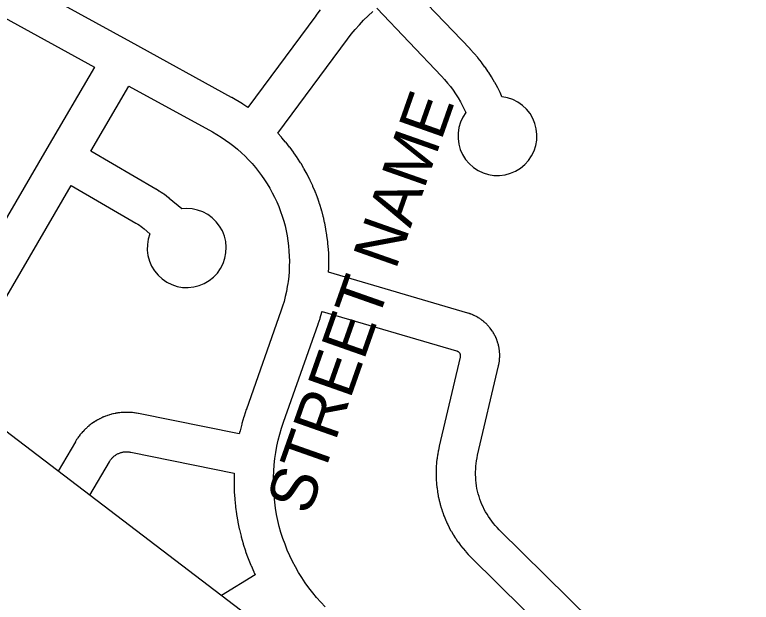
# Model space of a CAD drawing. Extents: x 599744 to 600217, y 4827560 to 4828065.
# Drawn here: x 600005.99 to 600017.17, y 4827965.06 to 4827973.98 of the extents above; entities that cross this region are included whole.
import ezdxf

# ---------------------------------------------------------------- set-up
doc = ezdxf.new("R2010")
doc.units = 0
doc.layers.add('G-ANNO-KEYP', color=7, linetype='Continuous')
doc.layers.add('G-TTLB-OTLN', color=7, linetype='Continuous')

msp = doc.modelspace()

# ---------------------------------------------------------------- linework, layer by layer
at = {"layer": 'G-ANNO-KEYP'}
for points in [[(600010.623, 4827974.058), (600010.559, 4827973.974), (600010.559, 4827973.974), (600010.555, 4827973.97), (600009.526, 4827972.575), (600009.523, 4827972.578), (600009.45, 4827972.626), (600009.449, 4827972.626), (600009.442, 4827972.632), (600009.367, 4827972.678), (600009.366, 4827972.678), (600009.358, 4827972.683), (600009.283, 4827972.726), (600009.282, 4827972.727), (600009.278, 4827972.729), (600007.753, 4827973.568), (600006.144, 4827974.453)], [(600013.694, 4827972.609), (600013.625, 4827972.657), (600013.549, 4827972.696), (600013.469, 4827972.723), (600013.386, 4827972.739), (600013.383, 4827972.74), (600013.359, 4827972.794), (600013.356, 4827972.797), (600013.354, 4827972.803), (600013.319, 4827972.875), (600013.316, 4827972.878), (600013.314, 4827972.884), (600013.276, 4827972.954), (600013.273, 4827972.958), (600013.271, 4827972.963), (600013.231, 4827973.032), (600013.227, 4827973.036), (600013.225, 4827973.041), (600013.182, 4827973.108), (600013.178, 4827973.113), (600013.176, 4827973.117), (600013.131, 4827973.183), (600013.127, 4827973.188), (600013.125, 4827973.191), (600013.078, 4827973.255), (600013.073, 4827973.26), (600013.071, 4827973.264), (600013.022, 4827973.326), (600013.016, 4827973.331), (600013.015, 4827973.334), (600012.963, 4827973.394), (600012.957, 4827973.4), (600012.956, 4827973.402), (600012.902, 4827973.461), (600012.899, 4827973.464), (600012.899, 4827973.465), (600011.989, 4827974.419)], [(600011.036, 4827973.613), (600011.095, 4827973.69), (600011.155, 4827973.763), (600011.218, 4827973.834), (600011.283, 4827973.903), (600011.351, 4827973.97), (600011.421, 4827974.034)], [(600011.481, 4827974.085), (600012.463, 4827973.054), (600012.512, 4827973.001), (600012.557, 4827972.948), (600012.6, 4827972.894), (600012.641, 4827972.839), (600012.68, 4827972.782), (600012.717, 4827972.724), (600012.752, 4827972.664), (600012.785, 4827972.604), (600012.815, 4827972.542), (600012.833, 4827972.502), (600012.788, 4827972.43), (600012.753, 4827972.353), (600012.729, 4827972.272), (600012.716, 4827972.188), (600012.716, 4827972.103), (600012.728, 4827972.019), (600012.751, 4827971.937), (600012.786, 4827971.86), (600012.831, 4827971.788), (600012.886, 4827971.724), (600012.95, 4827971.667), (600013.02, 4827971.621), (600013.097, 4827971.584), (600013.178, 4827971.559), (600013.262, 4827971.546), (600013.347, 4827971.544), (600013.431, 4827971.555), (600013.513, 4827971.577), (600013.591, 4827971.611), (600013.663, 4827971.655), (600013.728, 4827971.709), (600013.785, 4827971.771), (600013.833, 4827971.841), (600013.871, 4827971.918), (600013.897, 4827971.998), (600013.912, 4827972.082), (600013.914, 4827972.166), (600013.905, 4827972.251), (600013.884, 4827972.333), (600013.852, 4827972.411), (600013.809, 4827972.484), (600013.756, 4827972.55), (600013.694, 4827972.609)], [(600005.826, 4827973.944), (600007.195, 4827973.191), (600006.474, 4827971.954), (600004.55, 4827968.652)], [(600010.693, 4827970.822), (600010.692, 4827970.823), (600010.69, 4827970.832), (600010.671, 4827970.917), (600010.67, 4827970.918), (600010.668, 4827970.927), (600010.646, 4827971.012), (600010.645, 4827971.013), (600010.643, 4827971.022), (600010.617, 4827971.105), (600010.616, 4827971.107), (600010.614, 4827971.115), (600010.586, 4827971.198), (600010.584, 4827971.2), (600010.582, 4827971.207), (600010.551, 4827971.289), (600010.549, 4827971.292), (600010.547, 4827971.299), (600010.513, 4827971.379), (600010.511, 4827971.382), (600010.509, 4827971.389), (600010.472, 4827971.468), (600010.47, 4827971.471), (600010.468, 4827971.477), (600010.428, 4827971.555), (600010.425, 4827971.559), (600010.424, 4827971.564), (600010.382, 4827971.641), (600010.378, 4827971.645), (600010.376, 4827971.65), (600010.332, 4827971.725), (600010.328, 4827971.73), (600010.326, 4827971.734), (600010.279, 4827971.808), (600010.275, 4827971.812), (600010.273, 4827971.816), (600010.224, 4827971.888), (600010.219, 4827971.893), (600010.218, 4827971.897), (600010.165, 4827971.967), (600010.161, 4827971.972), (600010.159, 4827971.975), (600010.105, 4827972.043), (600010.099, 4827972.049), (600010.098, 4827972.051), (600010.041, 4827972.118), (600010.035, 4827972.123), (600010.034, 4827972.125), (600009.981, 4827972.184), (600011.036, 4827973.613)], [(600008.209, 4827971.286), (600008.176, 4827971.308), (600008.175, 4827971.308), (600008.168, 4827971.313), (600008.134, 4827971.334), (600008.133, 4827971.334), (600008.13, 4827971.336), (600007.142, 4827971.911), (600007.72, 4827972.902), (600008.988, 4827972.205), (600009.056, 4827972.166), (600009.122, 4827972.125), (600009.186, 4827972.082), (600009.249, 4827972.037), (600009.31, 4827971.99), (600009.369, 4827971.941), (600009.428, 4827971.89), (600009.483, 4827971.837), (600009.537, 4827971.781), (600009.59, 4827971.725), (600009.64, 4827971.666), (600009.688, 4827971.606), (600009.734, 4827971.544), (600009.778, 4827971.48), (600009.82, 4827971.415), (600009.859, 4827971.349), (600009.896, 4827971.281), (600009.931, 4827971.212), (600009.963, 4827971.142), (600009.993, 4827971.071), (600010.021, 4827970.999), (600010.046, 4827970.926), (600010.069, 4827970.852), (600010.089, 4827970.777), (600010.106, 4827970.702), (600010.121, 4827970.626), (600010.133, 4827970.55), (600010.143, 4827970.473), (600010.149, 4827970.397), (600010.154, 4827970.319), (600010.155, 4827970.242), (600010.154, 4827970.165), (600010.151, 4827970.088), (600010.145, 4827970.011), (600010.136, 4827969.934), (600010.131, 4827969.902), (600010.124, 4827969.858), (600010.11, 4827969.782), (600010.093, 4827969.707), (600010.074, 4827969.632), (600010.052, 4827969.558), (600010.027, 4827969.483)], [(600005.03, 4827968.286), (600006.841, 4827971.394), (600007.826, 4827970.82), (600007.853, 4827970.803), (600007.878, 4827970.787), (600007.903, 4827970.77), (600007.926, 4827970.753), (600007.951, 4827970.733), (600008.038, 4827970.66)], [(600008.038, 4827970.66), (600008.013, 4827970.579), (600007.999, 4827970.496), (600007.998, 4827970.411), (600008.008, 4827970.327), (600008.03, 4827970.245), (600008.064, 4827970.167), (600008.108, 4827970.095), (600008.162, 4827970.029), (600008.224, 4827969.972), (600008.294, 4827969.924), (600008.37, 4827969.886), (600008.451, 4827969.86), (600008.534, 4827969.845), (600008.619, 4827969.842), (600008.703, 4827969.851), (600008.785, 4827969.872), (600008.864, 4827969.904), (600008.937, 4827969.947), (600009.003, 4827970), (600009.062, 4827970.062), (600009.11, 4827970.131), (600009.149, 4827970.207), (600009.177, 4827970.287), (600009.193, 4827970.37), (600009.197, 4827970.455), (600009.189, 4827970.539), (600009.169, 4827970.622), (600009.138, 4827970.701), (600009.096, 4827970.774), (600009.045, 4827970.841), (600008.984, 4827970.901), (600008.915, 4827970.951), (600008.84, 4827970.99), (600008.761, 4827971.019), (600008.678, 4827971.036), (600008.593, 4827971.042), (600008.522, 4827971.037), (600008.331, 4827971.195), (600008.328, 4827971.198), (600008.328, 4827971.198), (600008.297, 4827971.223), (600008.294, 4827971.226), (600008.289, 4827971.229), (600008.257, 4827971.253), (600008.257, 4827971.253), (600008.249, 4827971.258), (600008.217, 4827971.281), (600008.216, 4827971.281), (600008.209, 4827971.286)], [(600013.065, 4827969.357), (600013.057, 4827969.363), (600013.046, 4827969.371), (600013.045, 4827969.371), (600013.037, 4827969.376), (600013.025, 4827969.384), (600013.024, 4827969.384), (600013.016, 4827969.389), (600013.004, 4827969.396), (600013.002, 4827969.396), (600012.995, 4827969.401), (600012.983, 4827969.407), (600012.98, 4827969.408), (600012.973, 4827969.412), (600012.961, 4827969.418), (600012.958, 4827969.419), (600012.951, 4827969.423), (600012.939, 4827969.428), (600012.935, 4827969.429), (600012.929, 4827969.432), (600012.916, 4827969.437), (600012.912, 4827969.438), (600012.906, 4827969.441), (600012.893, 4827969.445), (600012.889, 4827969.446), (600012.883, 4827969.449), (600012.87, 4827969.453), (600012.868, 4827969.453), (600012.865, 4827969.454), (600010.75, 4827970.075), (600010.753, 4827970.142), (600010.753, 4827970.15), (600010.753, 4827970.152), (600010.754, 4827970.24), (600010.754, 4827970.249), (600010.754, 4827970.25), (600010.752, 4827970.337), (600010.752, 4827970.347), (600010.752, 4827970.348), (600010.747, 4827970.435), (600010.746, 4827970.445), (600010.746, 4827970.445), (600010.738, 4827970.532), (600010.737, 4827970.542), (600010.737, 4827970.543), (600010.726, 4827970.629), (600010.726, 4827970.629), (600010.725, 4827970.64), (600010.711, 4827970.726), (600010.711, 4827970.726), (600010.709, 4827970.736), (600010.693, 4827970.822)], [(600010.027, 4827969.483), (600009.503, 4827967.994), (600009.502, 4827967.992), (600009.501, 4827967.989), (600009.468, 4827967.889), (600009.467, 4827967.884), (600009.465, 4827967.879), (600009.435, 4827967.779), (600009.435, 4827967.773), (600009.432, 4827967.768), (600009.406, 4827967.667), (600009.406, 4827967.661), (600009.404, 4827967.657), (600009.395, 4827967.618), (600007.863, 4827967.929), (600007.859, 4827967.929), (600007.857, 4827967.93), (600007.836, 4827967.934), (600007.83, 4827967.934), (600007.826, 4827967.936), (600007.805, 4827967.939), (600007.797, 4827967.939), (600007.794, 4827967.94), (600007.773, 4827967.943), (600007.765, 4827967.943), (600007.762, 4827967.944), (600007.741, 4827967.945), (600007.733, 4827967.945), (600007.73, 4827967.946), (600007.709, 4827967.947), (600007.7, 4827967.946), (600007.699, 4827967.947), (600007.677, 4827967.947), (600007.668, 4827967.947), (600007.666, 4827967.947), (600007.645, 4827967.946), (600007.635, 4827967.946), (600007.635, 4827967.946), (600007.613, 4827967.944), (600007.603, 4827967.943), (600007.603, 4827967.944), (600007.582, 4827967.941), (600007.575, 4827967.941), (600007.571, 4827967.94), (600007.55, 4827967.937), (600007.55, 4827967.937), (600007.539, 4827967.936), (600007.518, 4827967.932), (600007.518, 4827967.931), (600007.508, 4827967.93)], [(600010.699, 4827964.994), (600010.632, 4827965.064), (600010.569, 4827965.134), (600010.509, 4827965.207), (600010.451, 4827965.281), (600010.396, 4827965.358), (600010.343, 4827965.437), (600010.294, 4827965.517), (600010.247, 4827965.6), (600010.203, 4827965.683), (600010.162, 4827965.768), (600010.124, 4827965.855), (600010.089, 4827965.943), (600010.057, 4827966.032), (600010.028, 4827966.122), (600010.002, 4827966.213), (600009.98, 4827966.305), (600009.961, 4827966.397), (600009.945, 4827966.49), (600009.932, 4827966.584), (600009.923, 4827966.678), (600009.917, 4827966.773), (600009.914, 4827966.867), (600009.915, 4827966.962), (600009.919, 4827967.056), (600009.926, 4827967.15), (600009.936, 4827967.244), (600009.95, 4827967.338), (600009.967, 4827967.431), (600009.987, 4827967.523), (600010.011, 4827967.615), (600010.038, 4827967.705), (600010.068, 4827967.797), (600010.592, 4827969.286), (600010.593, 4827969.288), (600010.594, 4827969.29), (600010.622, 4827969.373), (600010.622, 4827969.378), (600010.625, 4827969.383), (600010.65, 4827969.467)], [(600010.65, 4827969.467), (600010.65, 4827969.472), (600010.652, 4827969.477), (600010.653, 4827969.479), (600012.694, 4827968.881), (600012.699, 4827968.879), (600012.702, 4827968.878), (600012.704, 4827968.877), (600012.707, 4827968.876), (600012.709, 4827968.875), (600012.712, 4827968.874), (600012.714, 4827968.872), (600012.716, 4827968.871), (600012.718, 4827968.869), (600012.721, 4827968.868), (600012.723, 4827968.866), (600012.725, 4827968.864), (600012.727, 4827968.862), (600012.729, 4827968.86), (600012.731, 4827968.858), (600012.732, 4827968.857), (600012.734, 4827968.854), (600012.736, 4827968.852), (600012.738, 4827968.85), (600012.739, 4827968.848), (600012.74, 4827968.845), (600012.742, 4827968.843), (600012.743, 4827968.841), (600012.744, 4827968.838), (600012.745, 4827968.835), (600012.746, 4827968.833), (600012.747, 4827968.831), (600012.748, 4827968.828), (600012.749, 4827968.825), (600012.749, 4827968.822), (600012.75, 4827968.82), (600012.75, 4827968.817), (600012.75, 4827968.814), (600012.751, 4827968.812), (600012.751, 4827968.809), (600012.751, 4827968.806), (600012.751, 4827968.804), (600012.75, 4827968.801), (600012.75, 4827968.798), (600012.75, 4827968.795), (600012.749, 4827968.793), (600012.748, 4827968.787), (600012.431, 4827967.432), (600012.43, 4827967.429), (600012.429, 4827967.426), (600012.418, 4827967.375), (600012.418, 4827967.368), (600012.416, 4827967.364), (600012.407, 4827967.312), (600012.407, 4827967.306), (600012.405, 4827967.302), (600012.398, 4827967.25), (600012.398, 4827967.242), (600012.396, 4827967.239), (600012.391, 4827967.187), (600012.391, 4827967.179), (600012.39, 4827967.176), (600012.386, 4827967.123), (600012.386, 4827967.115), (600012.386, 4827967.113), (600012.384, 4827967.06), (600012.384, 4827967.051), (600012.383, 4827967.05), (600012.383, 4827966.997), (600012.384, 4827966.987), (600012.384, 4827966.986), (600012.385, 4827966.933), (600012.386, 4827966.924), (600012.386, 4827966.923), (600012.39, 4827966.87), (600012.391, 4827966.86), (600012.39, 4827966.86), (600012.396, 4827966.807), (600012.397, 4827966.801), (600012.397, 4827966.797), (600012.405, 4827966.744)], [(600013.293, 4827969.077), (600013.291, 4827969.08), (600013.289, 4827969.087), (600013.283, 4827969.099), (600013.28, 4827969.103), (600013.278, 4827969.109), (600013.272, 4827969.121), (600013.269, 4827969.125), (600013.267, 4827969.13), (600013.261, 4827969.142), (600013.257, 4827969.146), (600013.255, 4827969.151), (600013.248, 4827969.163), (600013.244, 4827969.168), (600013.242, 4827969.172), (600013.235, 4827969.184), (600013.23, 4827969.188), (600013.229, 4827969.192), (600013.221, 4827969.203), (600013.216, 4827969.209), (600013.214, 4827969.212), (600013.206, 4827969.223), (600013.201, 4827969.228), (600013.2, 4827969.231), (600013.191, 4827969.242), (600013.185, 4827969.248), (600013.184, 4827969.25), (600013.175, 4827969.26), (600013.169, 4827969.266), (600013.168, 4827969.268), (600013.158, 4827969.278), (600013.151, 4827969.284), (600013.151, 4827969.285), (600013.141, 4827969.295), (600013.134, 4827969.301), (600013.133, 4827969.302), (600013.123, 4827969.311), (600013.115, 4827969.318), (600013.115, 4827969.319), (600013.104, 4827969.327), (600013.096, 4827969.334), (600013.096, 4827969.334), (600013.096, 4827969.334), (600013.096, 4827969.335), (600013.096, 4827969.335), (600013.086, 4827969.342), (600013.085, 4827969.343), (600013.077, 4827969.349), (600013.066, 4827969.357), (600013.065, 4827969.357)], [(600013.336, 4827968.672), (600013.336, 4827968.679), (600013.338, 4827968.683), (600013.34, 4827968.696), (600013.34, 4827968.703), (600013.342, 4827968.707), (600013.344, 4827968.72), (600013.344, 4827968.728), (600013.345, 4827968.731), (600013.347, 4827968.744), (600013.347, 4827968.752), (600013.348, 4827968.755), (600013.348, 4827968.768), (600013.348, 4827968.777), (600013.349, 4827968.779), (600013.349, 4827968.793), (600013.349, 4827968.802), (600013.35, 4827968.804), (600013.349, 4827968.817), (600013.349, 4827968.827), (600013.349, 4827968.828), (600013.349, 4827968.841), (600013.348, 4827968.852), (600013.348, 4827968.852), (600013.347, 4827968.866), (600013.346, 4827968.876), (600013.346, 4827968.876), (600013.344, 4827968.89), (600013.344, 4827968.893), (600013.343, 4827968.901), (600013.341, 4827968.914), (600013.341, 4827968.914), (600013.339, 4827968.925), (600013.337, 4827968.938), (600013.336, 4827968.939), (600013.335, 4827968.948), (600013.332, 4827968.962), (600013.331, 4827968.963), (600013.329, 4827968.972), (600013.326, 4827968.985), (600013.325, 4827968.987), (600013.323, 4827968.995), (600013.319, 4827969.008), (600013.317, 4827969.01), (600013.315, 4827969.019), (600013.311, 4827969.032), (600013.309, 4827969.034), (600013.307, 4827969.042), (600013.303, 4827969.055), (600013.3, 4827969.057), (600013.299, 4827969.065), (600013.293, 4827969.077)], [(600015.444, 4827964.088), (600013.341, 4827966.165), (600013.309, 4827966.197), (600013.281, 4827966.228), (600013.253, 4827966.261), (600013.227, 4827966.294), (600013.202, 4827966.328), (600013.178, 4827966.363), (600013.156, 4827966.399), (600013.135, 4827966.435), (600013.115, 4827966.473), (600013.096, 4827966.51), (600013.079, 4827966.549), (600013.063, 4827966.588), (600013.048, 4827966.628), (600013.035, 4827966.668), (600013.023, 4827966.709), (600013.013, 4827966.75), (600013.004, 4827966.791), (600012.997, 4827966.833), (600012.991, 4827966.875), (600012.986, 4827966.917), (600012.984, 4827966.959), (600012.982, 4827967.001), (600012.982, 4827967.044), (600012.984, 4827967.086), (600012.987, 4827967.128), (600012.991, 4827967.17), (600012.997, 4827967.212), (600013.005, 4827967.254), (600013.014, 4827967.297), (600013.332, 4827968.653), (600013.332, 4827968.657), (600013.333, 4827968.659), (600013.336, 4827968.672)], [(600007.508, 4827967.93), (600007.487, 4827967.925), (600007.486, 4827967.925), (600007.476, 4827967.923), (600007.456, 4827967.918), (600007.454, 4827967.917), (600007.446, 4827967.915), (600007.425, 4827967.909), (600007.423, 4827967.908), (600007.415, 4827967.906), (600007.395, 4827967.899), (600007.392, 4827967.898), (600007.384, 4827967.896), (600007.364, 4827967.889), (600007.362, 4827967.887), (600007.355, 4827967.885), (600007.335, 4827967.877), (600007.332, 4827967.875), (600007.325, 4827967.873), (600007.306, 4827967.864), (600007.302, 4827967.861), (600007.296, 4827967.859), (600007.277, 4827967.85), (600007.273, 4827967.847), (600007.267, 4827967.845), (600007.248, 4827967.835), (600007.244, 4827967.832), (600007.239, 4827967.83), (600007.221, 4827967.819), (600007.216, 4827967.815), (600007.212, 4827967.813), (600007.194, 4827967.802), (600007.189, 4827967.798), (600007.185, 4827967.796), (600007.167, 4827967.784), (600007.162, 4827967.78), (600007.158, 4827967.778), (600007.141, 4827967.765), (600007.136, 4827967.76), (600007.133, 4827967.759), (600007.116, 4827967.746), (600007.111, 4827967.74), (600007.108, 4827967.739), (600007.092, 4827967.725), (600007.086, 4827967.719), (600007.084, 4827967.718), (600007.068, 4827967.704), (600007.062, 4827967.697), (600007.06, 4827967.696), (600007.045, 4827967.681), (600007.039, 4827967.674), (600007.037, 4827967.674)], [(600007.037, 4827967.674), (600007.023, 4827967.658), (600007.017, 4827967.651), (600007.016, 4827967.65), (600007.002, 4827967.634), (600006.995, 4827967.626), (600006.995, 4827967.626), (600006.981, 4827967.61), (600006.976, 4827967.604), (600006.975, 4827967.601), (600006.962, 4827967.584), (600006.962, 4827967.584), (600006.955, 4827967.576), (600006.943, 4827967.558), (600006.943, 4827967.558), (600006.937, 4827967.55), (600006.925, 4827967.532), (600006.925, 4827967.531), (600006.92, 4827967.523), (600006.908, 4827967.504), (600006.908, 4827967.503), (600006.906, 4827967.5), (600006.646, 4827967.053)], [(600007.126, 4827966.687), (600007.422, 4827967.196), (600007.429, 4827967.208), (600007.435, 4827967.217), (600007.441, 4827967.226), (600007.448, 4827967.234), (600007.454, 4827967.242), (600007.461, 4827967.25), (600007.469, 4827967.258), (600007.476, 4827967.266), (600007.484, 4827967.273), (600007.492, 4827967.28), (600007.501, 4827967.286), (600007.51, 4827967.293), (600007.518, 4827967.299), (600007.527, 4827967.305), (600007.536, 4827967.31), (600007.546, 4827967.315), (600007.556, 4827967.32), (600007.565, 4827967.324), (600007.575, 4827967.328), (600007.585, 4827967.332), (600007.595, 4827967.335), (600007.605, 4827967.338), (600007.616, 4827967.341), (600007.626, 4827967.343)], [(600007.626, 4827967.343), (600007.637, 4827967.345), (600007.648, 4827967.346), (600007.658, 4827967.347), (600007.669, 4827967.348), (600007.68, 4827967.348), (600007.69, 4827967.348), (600007.701, 4827967.348), (600007.712, 4827967.347), (600007.722, 4827967.346), (600007.733, 4827967.344), (600007.746, 4827967.342), (600009.318, 4827967.022), (600009.316, 4827966.981), (600009.317, 4827966.972), (600009.316, 4827966.97), (600009.315, 4827966.865), (600009.316, 4827966.856), (600009.316, 4827966.855), (600009.319, 4827966.75), (600009.319, 4827966.74), (600009.319, 4827966.739), (600009.326, 4827966.635), (600009.327, 4827966.625), (600009.327, 4827966.624), (600009.337, 4827966.52), (600009.338, 4827966.512), (600009.338, 4827966.509), (600009.352, 4827966.405), (600009.352, 4827966.405), (600009.354, 4827966.395), (600009.371, 4827966.291), (600009.372, 4827966.291), (600009.373, 4827966.281), (600009.395, 4827966.178), (600009.395, 4827966.177), (600009.397, 4827966.168), (600009.422, 4827966.066), (600009.423, 4827966.065), (600009.424, 4827966.056), (600009.453, 4827965.955), (600009.454, 4827965.953), (600009.456, 4827965.945), (600009.488, 4827965.845), (600009.489, 4827965.842), (600009.491, 4827965.835), (600009.527, 4827965.736), (600009.528, 4827965.733), (600009.53, 4827965.726), (600009.569, 4827965.628)], [(600012.405, 4827966.744), (600012.405, 4827966.744), (600012.406, 4827966.734), (600012.415, 4827966.682), (600012.416, 4827966.681), (600012.417, 4827966.671), (600012.429, 4827966.62), (600012.429, 4827966.619), (600012.431, 4827966.609), (600012.444, 4827966.558), (600012.445, 4827966.557), (600012.446, 4827966.548), (600012.461, 4827966.497), (600012.462, 4827966.495), (600012.464, 4827966.487), (600012.481, 4827966.437), (600012.482, 4827966.435), (600012.484, 4827966.427), (600012.502, 4827966.377), (600012.504, 4827966.375), (600012.506, 4827966.368), (600012.526, 4827966.319), (600012.528, 4827966.316), (600012.53, 4827966.309), (600012.552, 4827966.261), (600012.554, 4827966.257), (600012.556, 4827966.251), (600012.58, 4827966.204), (600012.583, 4827966.2), (600012.584, 4827966.194), (600012.609, 4827966.148), (600012.613, 4827966.144), (600012.615, 4827966.138), (600012.641, 4827966.093), (600012.645, 4827966.088), (600012.647, 4827966.084), (600012.675, 4827966.039), (600012.679, 4827966.034), (600012.681, 4827966.03), (600012.71, 4827965.987), (600012.715, 4827965.982), (600012.716, 4827965.978), (600012.748, 4827965.935), (600012.753, 4827965.93), (600012.754, 4827965.927), (600012.787, 4827965.886), (600012.792, 4827965.88), (600012.793, 4827965.877), (600012.828, 4827965.837), (600012.834, 4827965.831)], [(600012.834, 4827965.831), (600012.835, 4827965.829), (600012.87, 4827965.79), (600012.877, 4827965.784), (600012.877, 4827965.782), (600012.914, 4827965.745), (600012.918, 4827965.742), (600012.918, 4827965.741), (600014.9, 4827963.784)], [(600009.569, 4827965.628), (600009.571, 4827965.626), (600009.573, 4827965.619), (600009.616, 4827965.523), (600009.618, 4827965.519), (600009.62, 4827965.513), (600009.637, 4827965.477), (600009.123, 4827965.163)]]:
    msp.add_lwpolyline(points, dxfattribs=at)
at = {"layer": 'G-TTLB-OTLN'}
msp.add_lwpolyline([(599983.747, 4827984.522), (600022.202, 4828034.93), (600058.02, 4828007.605), (600019.565, 4827957.197)], close=True, dxfattribs=at)

# ---------------------------------------------------------------- texts
at = {"layer": 'G-ANNO-KEYP'}
msp.add_text('STREET NAME', height=0.7, rotation=70.5967, dxfattribs=at).set_placement((600010.455, 4827966.369))

doc.saveas('drawing.dxf')
